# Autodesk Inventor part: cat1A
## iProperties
Created: 2002-07
Part Number: cat1A
Document SubType Name: Modeling
Designer: Administrator
Control State: 0
Master: False
Checked Out: False
Shininess: 64.0
Length Units: 11269
Angle Units: 11279
Time Units: 11290
Mass Units: 11283
Length Display Precision: 3
Angle Display Precision: 2
Density: 0.0
Volumn: 0.0
Area: 0.0
PropertySet Name: Model Information
Author: Administrator
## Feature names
1. Extrusion1
2. Extrusion2
3. Extrusion3
4. Extrusion4
